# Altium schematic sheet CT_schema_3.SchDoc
size 398 x 269 mm
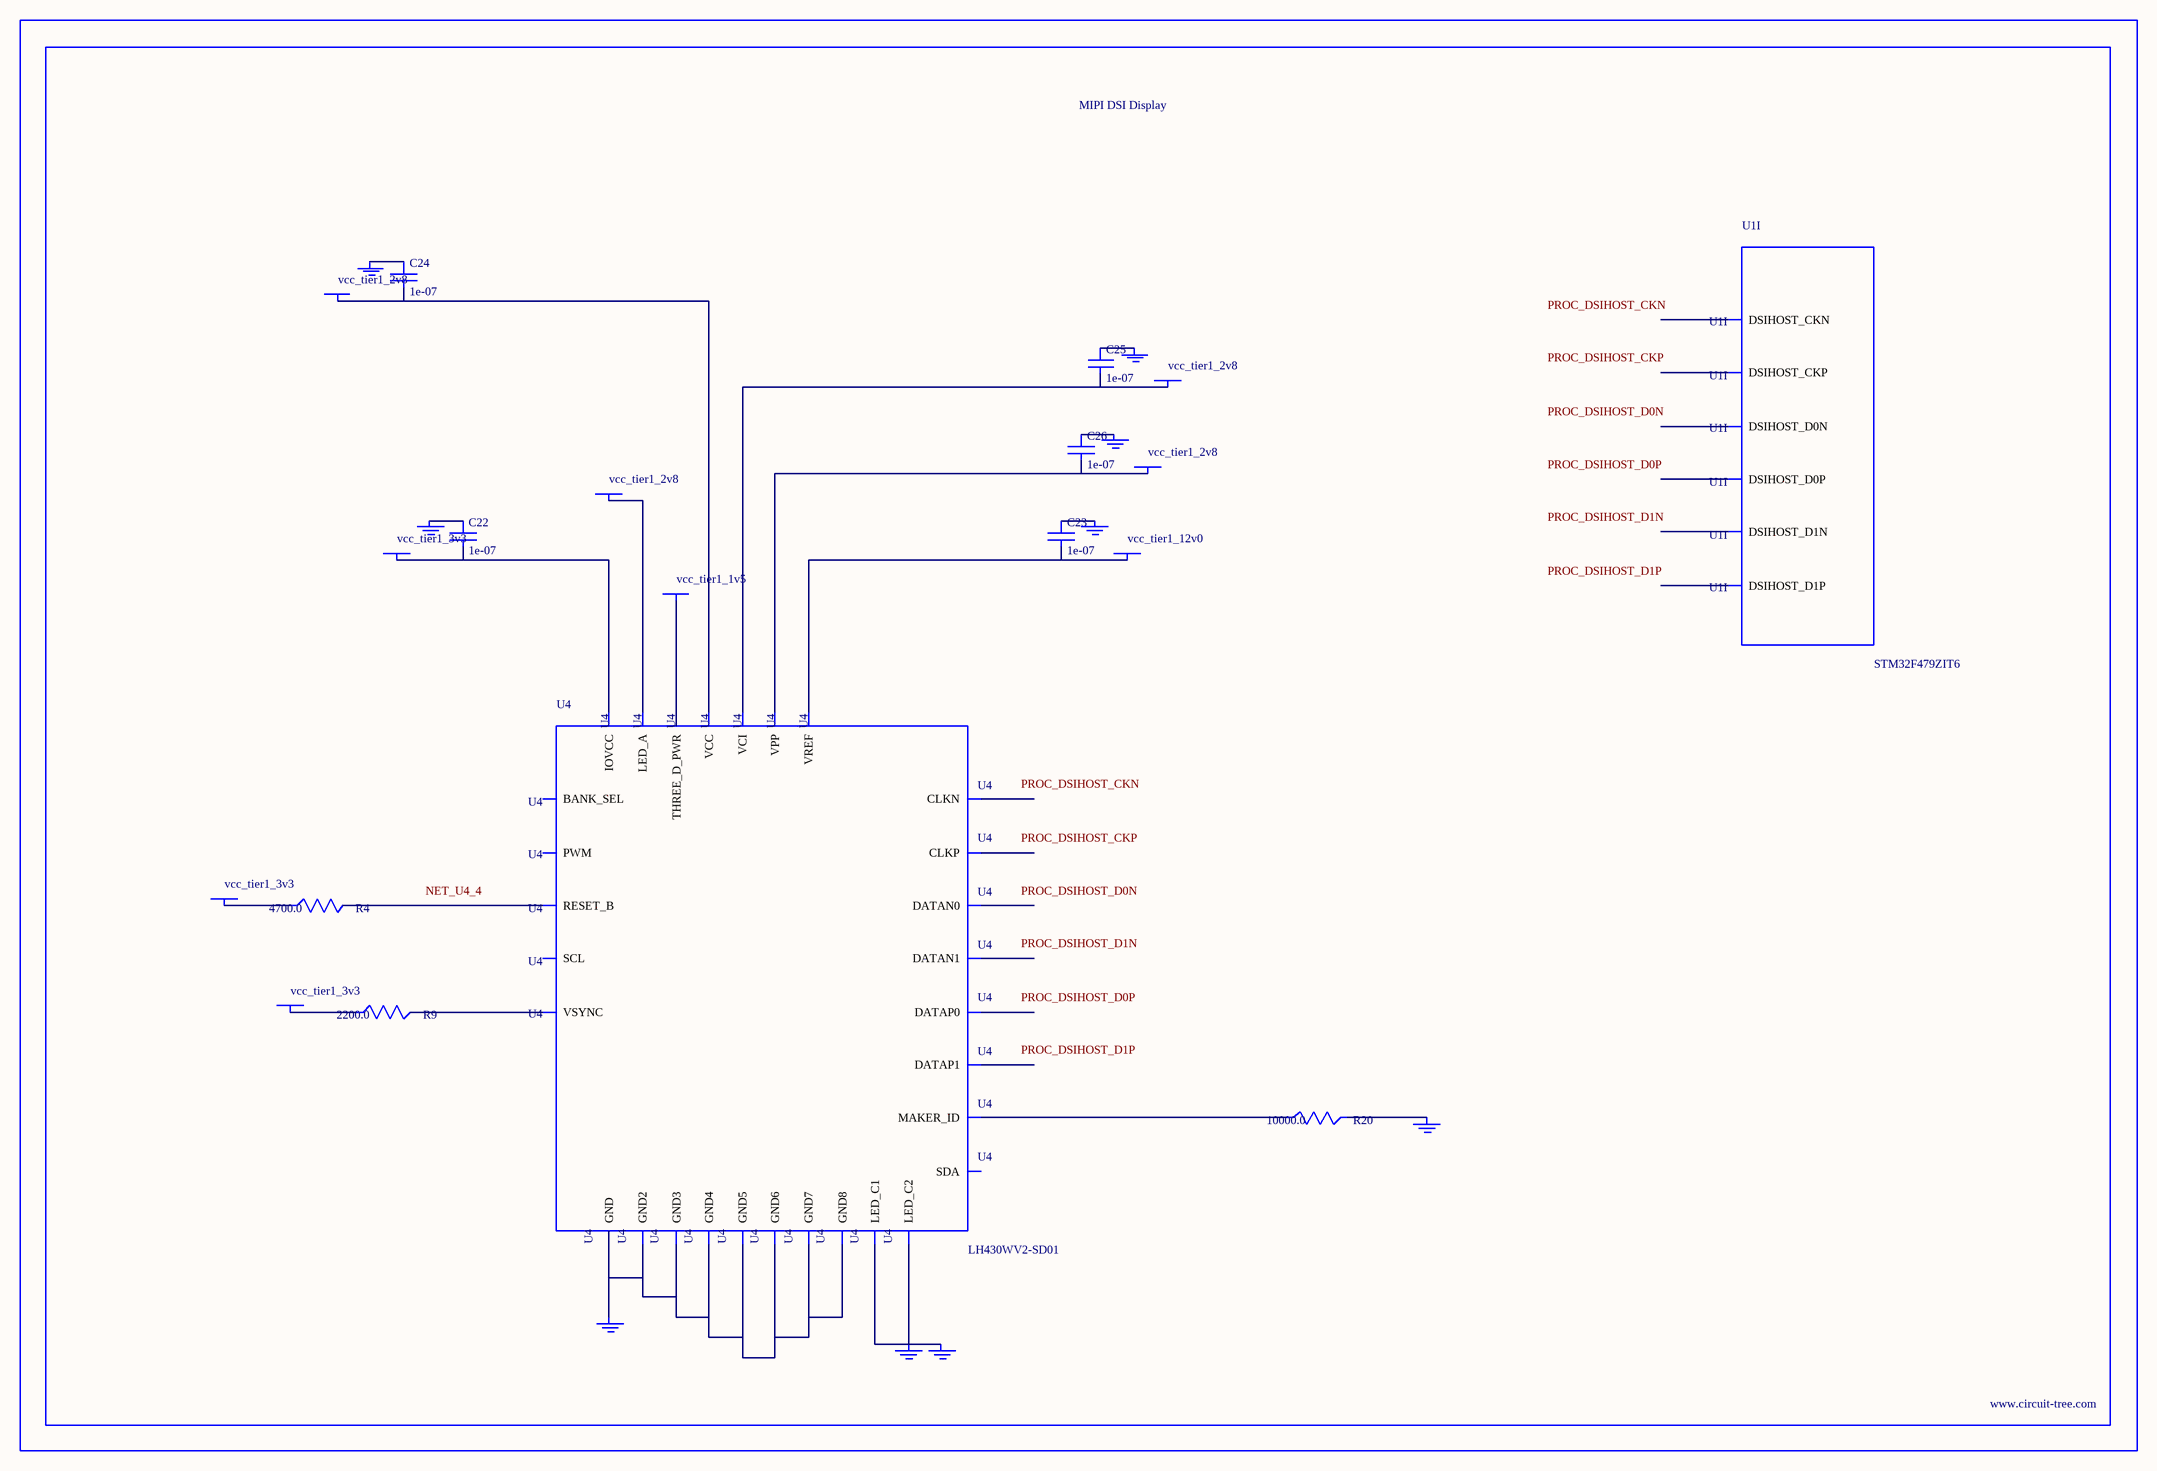
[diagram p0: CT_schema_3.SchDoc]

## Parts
BORDER2  (no value)
C22  1e-07  [C0402]
C23  1e-07  [C0402]
C24  1e-07  [C0402]
C25  1e-07  [C0402]
C26  1e-07  [C0402]
GND_INSTANCE_2_0  (no value)
GND_INSTANCE_2_1  (no value)
GND_INSTANCE_2_2  (no value)
GND_INSTANCE_2_3  (no value)
GND_INSTANCE_2_4  (no value)
GND_INSTANCE_2_5  (no value)
GND_INSTANCE_2_6  (no value)
GND_INSTANCE_2_7  (no value)
GND_INSTANCE_2_8  (no value)
POWER_INSTANCE_2_0  vcc_tier1_3v3
POWER_INSTANCE_2_1  vcc_tier1_2v8
POWER_INSTANCE_2_2  vcc_tier1_2v8
POWER_INSTANCE_2_3  vcc_tier1_2v8
POWER_INSTANCE_2_4  vcc_tier1_2v8
POWER_INSTANCE_2_5  vcc_tier1_12v0
POWER_INSTANCE_2_6  vcc_tier1_3v3
POWER_INSTANCE_2_7  vcc_tier1_3v3
POWER_INSTANCE_2_8  vcc_tier1_1v5
R4  4700.0  [R0603]
R9  2200.0  [R0603]
R20  10000.0  [R0603]
U1  STM32F479ZIT6  [LQFP144]  (part I of 13)
U4  LH430WV2-SD01  [LH430WV2-SD01]

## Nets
NetC22_1: C22.1 GND_INSTANCE_2_0.0(GND)
NetC22_2: C22.2 POWER_INSTANCE_2_0.0(PWR) U4.2(IOVCC)
NetC23_1: C23.1 GND_INSTANCE_2_7.0(GND)
NetC23_2: C23.2 POWER_INSTANCE_2_5.0(PWR) U4.30(VREF)
NetC24_1: C24.1 GND_INSTANCE_2_5.0(GND)
NetC24_2: C24.2 POWER_INSTANCE_2_3.0(PWR) U4.22(VCC)
NetC25_1: C25.1 GND_INSTANCE_2_4.0(GND)
NetC25_2: C25.2 POWER_INSTANCE_2_2.0(PWR) U4.21(VCI)
NetC26_1: C26.1 GND_INSTANCE_2_6.0(GND)
NetC26_2: C26.2 POWER_INSTANCE_2_4.0(PWR) U4.23(VPP)
NetGND_INSTANCE_2_1_0: GND_INSTANCE_2_1.0(GND) GND_INSTANCE_2_2.0(GND) U4.17(LED_C1) U4.18(LED_C2)
NetGND_INSTANCE_2_3_0: GND_INSTANCE_2_3.0(GND) R20.2
NetGND_INSTANCE_2_8_0: GND_INSTANCE_2_8.0(GND) U4.1(GND) U4.6(GND2) U4.9(GND3) U4.12(GND4) U4.15(GND5) U4.19(GND6) U4.24(GND7) U4.27(GND8)
NetPOWER_INSTANCE_2_1_0: POWER_INSTANCE_2_1.0(PWR) U4.16(LED_A)
NetPOWER_INSTANCE_2_6_0: POWER_INSTANCE_2_6.0(PWR) R4.1
NetPOWER_INSTANCE_2_7_0: POWER_INSTANCE_2_7.0(PWR) R9.1
NetPOWER_INSTANCE_2_8_0: POWER_INSTANCE_2_8.0(PWR) U4.29(THREE_D_PWR)
NetR4_2: R4.2 U4.4(RESET_B)
NetR9_2: R9.2 U4.5(VSYNC)
NetR20_1: R20.1 U4.20(MAKER_ID)

Not connected (* = marked no-connect by the designer): U1 82(DSIHOST_D0P) 83(DSIHOST_D0N) 85(DSIHOST_CKP) 86(DSIHOST_CKN) 88(DSIHOST_D1P) 89(DSIHOST_D1N); U4 3(PWM) 7(DATAN0) 8(DATAP0) 10(DATAN1) 11(DATAP1) 13(CLKN) 14(CLKP) 25(SCL) 26(SDA) 28(BANK_SEL)

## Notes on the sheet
- Labels drawn without touching a wire or pin: NET_U4_4, PROC_DSIHOST_CKN, PROC_DSIHOST_CKP, PROC_DSIHOST_D0N, PROC_DSIHOST_D0P, PROC_DSIHOST_D1N, PROC_DSIHOST_D1P

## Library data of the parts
BORDER2 = BORDER_PAGE2
C22-C26 = C0402C104K3RACTU
GND_INSTANCE_2_0-GND_INSTANCE_2_8 = GND
POWER_INSTANCE_2_0-POWER_INSTANCE_2_8 = PWR
R4 = RC0603JR-074K7L
R9 = RC0603JR-072K2L
R20 = RC0603JR-0710KL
